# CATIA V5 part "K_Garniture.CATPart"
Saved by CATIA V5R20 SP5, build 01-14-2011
Part number: Garniture
Bounding box of the stored display mesh (mm): x 0 to 50, y 12 to 42, z 10.5 to 18
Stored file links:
  G:\Khaled_CFAO_2011\ST2M\ST2M_GR1\lpierredon\Khaled\CAD_thinkMOTION\K_Garniture.CATPart
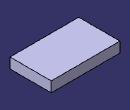
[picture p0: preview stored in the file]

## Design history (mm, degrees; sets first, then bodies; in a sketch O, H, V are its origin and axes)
Body1 (main body)
  Sketch1 on yz-plane, origin (0, 0, 0), H (0, 1, 0), V (0, 0, 1)
    line L1 (12, 18) -> (42, 18)
    line L2 (42, 18) -> (42, 10.5)
    line L3 (42, 10.5) -> (12, 10.5)
    line L4 (12, 10.5) -> (12, 18)
    length L2 = 7.5
    length L1 = 30
    horizontal: L1 H, L3 H
    vertical: L2 V, L4 V
  Pad1: profile Sketch1, direction (1, 0, 0), length 50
